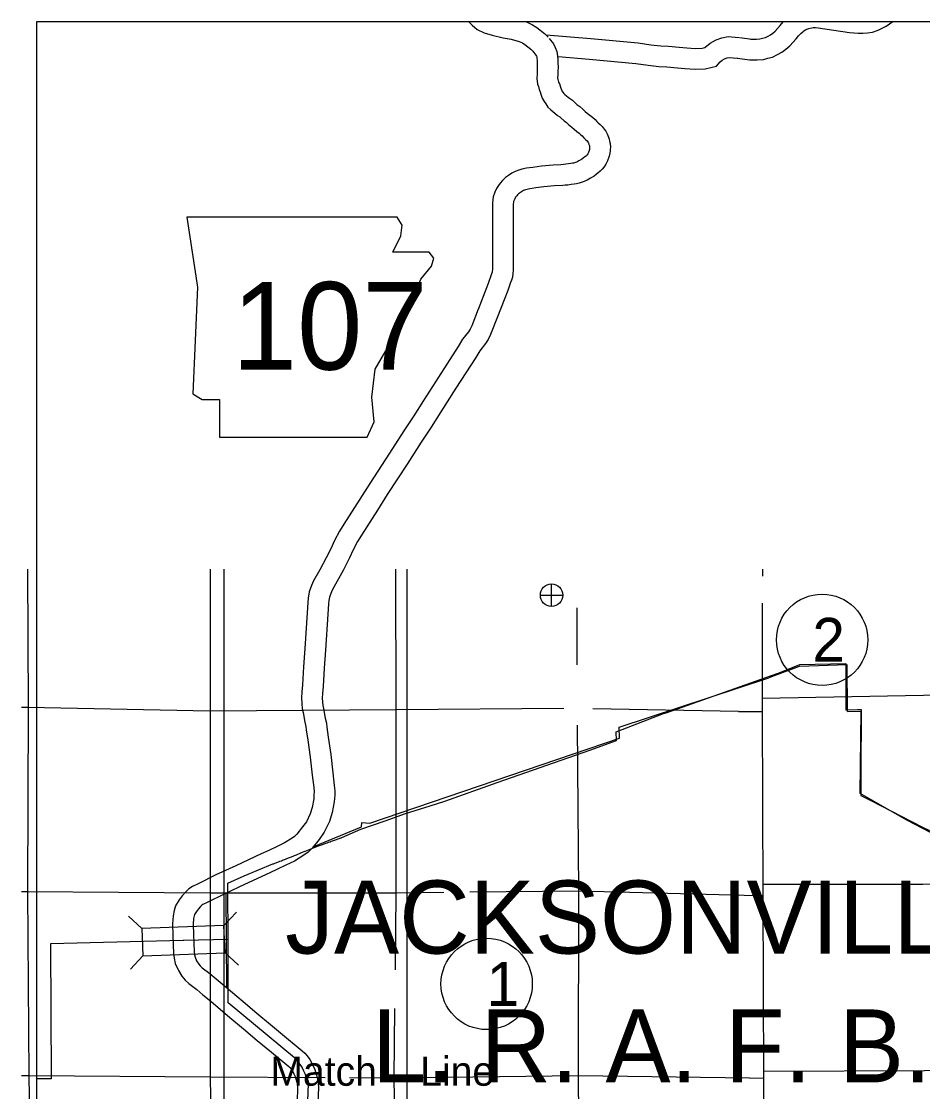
# Model space of a CAD drawing. Extents: x 1127717 to 1741049, y 2026793 to 2244711.
# Drawn here: x 1238326 to 1244840, y 2147909 to 2155644 of the extents above; entities that cross this region are included whole.
import ezdxf

# ---------------------------------------------------------------- set-up
doc = ezdxf.new("R2010")
doc.units = 0
for name, color, linetype in [('1', 7, 'Continuous'), ('10', 7, 'Continuous'), ('20', 7, 'Continuous'), ('21', 7, 'Continuous'), ('26', 7, 'Continuous'), ('27', 7, 'Continuous'), ('30', 7, 'Continuous'), ('4', 7, 'Continuous'), ('5', 7, 'Continuous'), ('58', 7, 'Continuous'), ('6', 7, 'Continuous'), ('7', 7, 'Continuous')]:
    doc.layers.add(name, color=color, linetype=linetype)

msp = doc.modelspace()

# ---------------------------------------------------------------- linework, layer by layer
at = {"layer": '1'}
msp.add_lwpolyline([(1238438.2, 2155644.2), (1269451.6, 2155644.2), (1269451.6, 2123596.1), (1238438.2, 2123596.1)], close=True, dxfattribs=at)
at = {"layer": '10'}
for points in [[(1241557.7, 2155644.2), (1241583.2, 2155615.8), (1241620.5, 2155586.1), (1241670.8, 2155562.5), (1241729.9, 2155544.7), (1241807.2, 2155526.2), (1241865.2, 2155515.5), (1241924.6, 2155499.4), (1241947.4, 2155488.5), (1241964.2, 2155478.1), (1242008.5, 2155443.1), (1242029, 2155422.7)], [(1241963.7, 2155644.2), (1241976.8, 2155640.6), (1242019.6, 2155620.3), (1242050.6, 2155601), (1242108.1, 2155555.6), (1242134.7, 2155529.2)], [(1243591, 2155366.7), (1243643.7, 2155366.1), (1243689.8, 2155369.7), (1243720.9, 2155378.4), (1243754.5, 2155386.5), (1243791.3, 2155403.9), (1243822.6, 2155421.2), (1243851.2, 2155442.7), (1243879.6, 2155466.7), (1243925.4, 2155518.7), (1243942.2, 2155539.5), (1243960.2, 2155557.1), (1243973.4, 2155569.6), (1243982.5, 2155577), (1243993.5, 2155583.8), (1244004.1, 2155589.2), (1244017.6, 2155592.2), (1244038.4, 2155598.5), (1244048.5, 2155600.6), (1244056.5, 2155601), (1244065.1, 2155601), (1244084.2, 2155597.4), (1244310.3, 2155565.2), (1244373.8, 2155558.4), (1244407.3, 2155558.5), (1244441.9, 2155562.2), (1244478.2, 2155567.3), (1244519.8, 2155579.8), (1244575.7, 2155610), (1244601.5, 2155626.9), (1244624, 2155644.2)], [(1243597, 2155516.6), (1243638.7, 2155516.1), (1243663.5, 2155518.1), (1243683.1, 2155523.6), (1243704.2, 2155528.7), (1243722.9, 2155537.5), (1243741, 2155547.5), (1243757.7, 2155560.1), (1243774.4, 2155574.2), (1243810.7, 2155615.4), (1243831, 2155640.6), (1243834.7, 2155644.2)], [(1242118.7, 2155548.1), (1242441.9, 2155520.2), (1242785.2, 2155489.3), (1242875.3, 2155475.6), (1242946.8, 2155468.4), (1243002.4, 2155464.5), (1243080.1, 2155458.6), (1243134.9, 2155453.5), (1243196.7, 2155448.3), (1243246.5, 2155451.3), (1243266.4, 2155456.1), (1243304.1, 2155486.5), (1243347.2, 2155512.1), (1243387.7, 2155524.8), (1243434.3, 2155536), (1243484.3, 2155529.5), (1243514.7, 2155527.5)], [(1242141.2, 2155521.8), (1242172.2, 2155481.6), (1242185.1, 2155456.7), (1242197.3, 2155427.8), (1242201.3, 2155392.9), (1242203.2, 2155365.6), (1242203.8, 2155341.8), (1242205, 2155315.5), (1242203.8, 2155281.4), (1242203.3, 2155258.8), (1242201.9, 2155236.4), (1242203.3, 2155224.5), (1242206.8, 2155214.5), (1242208.7, 2155206.2), (1242215.9, 2155193.1), (1242225.3, 2155162.2), (1242229.4, 2155148.7), (1242233, 2155142.5), (1242239.9, 2155131.7), (1242245.6, 2155123.8), (1242253, 2155116.7), (1242265.2, 2155106.5), (1242277.5, 2155095.7), (1242286.7, 2155088.4), (1242309.1, 2155075.3), (1242328.7, 2155055.9), (1242341.6, 2155044), (1242362.3, 2155029.9), (1242383.9, 2155008.8), (1242401.1, 2154993.3), (1242416.5, 2154980.9), (1242434.6, 2154965.5), (1242453.6, 2154951.6), (1242472.6, 2154934.1), (1242485, 2154921.3), (1242495.1, 2154911.3), (1242508.3, 2154898.7), (1242523.5, 2154883.6), (1242538.8, 2154866.2), (1242549.5, 2154850.1), (1242560.4, 2154830.5), (1242568.7, 2154808.6), (1242574.2, 2154794.1), (1242578, 2154778.1), (1242581.1, 2154761.7), (1242584.4, 2154735.3), (1242582.5, 2154719.7), (1242582.2, 2154708.2), (1242579.4, 2154690.7), (1242574.9, 2154669.4), (1242562.9, 2154636), (1242549.9, 2154611.9), (1242538.5, 2154594.2), (1242524.8, 2154576.2), (1242509.5, 2154561.7), (1242492.5, 2154547.4), (1242482.1, 2154539.4), (1242465, 2154524.6), (1242440, 2154510.3), (1242427.2, 2154504.9), (1242415.4, 2154497), (1242393.6, 2154486.7), (1242378.1, 2154481.7), (1242357.2, 2154474.3), (1242337.3, 2154471.2), (1242322.4, 2154467.9), (1242299.9, 2154465.6), (1242275.3, 2154461.6), (1242257.2, 2154461.1), (1242238.7, 2154458.1), (1242179.7, 2154456), (1242103, 2154448.1), (1242044.1, 2154440.8), (1242018.1, 2154436.4), (1242000.5, 2154434.6), (1241981.2, 2154430.4), (1241970, 2154427), (1241955.4, 2154421.6), (1241947.5, 2154417.7), (1241933.3, 2154407.9), (1241920, 2154398.1), (1241912, 2154391), (1241906.6, 2154384.2), (1241898.6, 2154373.4), (1241891.9, 2154362.6), (1241886.6, 2154352), (1241883.8, 2154343.3), (1241882.9, 2154336.9), (1241881.7, 2154323.3), (1241880.5, 2154300.4), (1241880.1, 2154280.2), (1241880, 2154245.5), (1241880.9, 2153986.5), (1241880, 2153847.4), (1241878.8, 2153823), (1241875.5, 2153796.8), (1241868.2, 2153773.5), (1241861.4, 2153757.7), (1241841.8, 2153698.9), (1241814.5, 2153631.7), (1241768.1, 2153509.6)], [(1243519.1, 2155527.1), (1243605.7, 2155516)], [(1242022.5, 2155430.2), (1242045.2, 2155400.7), (1242049.2, 2155393), (1242050.8, 2155389.2), (1242051.9, 2155379.2), (1242053.3, 2155358.6), (1242053.9, 2155336.3), (1242054.9, 2155314.7), (1242053.8, 2155285.6), (1242053.4, 2155265.1), (1242051.3, 2155232.3), (1242056.3, 2155190.4), (1242062.6, 2155172.6), (1242067.4, 2155152.1), (1242076.9, 2155134.6), (1242081.7, 2155118.8), (1242090.8, 2155088.6), (1242105, 2155064.3), (1242115.7, 2155047.5), (1242131.8, 2155025), (1242153, 2155004.8), (1242167.4, 2154992.7), (1242181.6, 2154980.2), (1242202, 2154964.2), (1242217, 2154955.4), (1242225.1, 2154947.4), (1242248, 2154926.3), (1242266.9, 2154913.4), (1242281.1, 2154899.5), (1242303.8, 2154879), (1242321, 2154865.3), (1242341.6, 2154847.7), (1242358.3, 2154835.5), (1242367.8, 2154826.7), (1242378.1, 2154816.1), (1242390.5, 2154803.8), (1242403.9, 2154791), (1242414.2, 2154780.8), (1242419.5, 2154774.8), (1242421.3, 2154772.1), (1242424, 2154767.1), (1242428.5, 2154755.3), (1242430.5, 2154750), (1242431.2, 2154747), (1242432.8, 2154738.6), (1242433.3, 2154735), (1242432.7, 2154730.6), (1242432.5, 2154722), (1242431.9, 2154718.4), (1242430.3, 2154710.5), (1242425.5, 2154697.3), (1242420.5, 2154688), (1242415.5, 2154680.2), (1242412.9, 2154676.8), (1242409.6, 2154673.7), (1242398.4, 2154664.2), (1242387.2, 2154655.6), (1242378, 2154647.6), (1242373.5, 2154645.1), (1242355.7, 2154637.6), (1242341.1, 2154627.8), (1242338.2, 2154626.4), (1242330, 2154623.8), (1242320.2, 2154620.3), (1242309.4, 2154618.6), (1242298.5, 2154616.2), (1242280.2, 2154614.4), (1242261.1, 2154611.2), (1242243.3, 2154610.7), (1242224.1, 2154607.7), (1242169.4, 2154605.7), (1242086, 2154597.2), (1242022.5, 2154589.2), (1241998, 2154585.2), (1241976.7, 2154582.9), (1241943.5, 2154575.7), (1241922, 2154569.2), (1241896.1, 2154559.5), (1241871.5, 2154547.5), (1241846.5, 2154530.2), (1241825.6, 2154515), (1241802.4, 2154494.2), (1241787.5, 2154475.4), (1241774.3, 2154457.6), (1241760.9, 2154435.9), (1241747.3, 2154408.9), (1241737.2, 2154377.1), (1241733.9, 2154354.4), (1241732, 2154333.9), (1241730.5, 2154305.7), (1241730.1, 2154281.8), (1241730, 2154245.4), (1241730.9, 2153986.8), (1241730, 2153851.5), (1241729.2, 2153835.9), (1241728.4, 2153828.9), (1241727.5, 2153826), (1241721.1, 2153811.3), (1241701, 2153750.9), (1241674.8, 2153686.5), (1241627.9, 2153562.8)], [(1242204.7, 2155390.1), (1242428.7, 2155370.8), (1242767.2, 2155340.3), (1242856.5, 2155326.8), (1242934, 2155319), (1242991.4, 2155314.9), (1243067.5, 2155309.1), (1243121.7, 2155304.1), (1243194.9, 2155297.9), (1243268.7, 2155302.3), (1243349.5, 2155321.8), (1243376.5, 2155352.2), (1243390, 2155363), (1243408.8, 2155374.2), (1243427.7, 2155380.1), (1243442.5, 2155383.7), (1243469.6, 2155380.2), (1243504.6, 2155377.8)], [(1243500.2, 2155378.3), (1243591, 2155366.7)], [(1241628.3, 2153563.7), (1241580.7, 2153443.2), (1241568.6, 2153420.6), (1241556.6, 2153401), (1241514.9, 2153347), (1241483.6, 2153294.9), (1241341, 2153073.7), (1241231.5, 2152903.1), (1241162.3, 2152793), (1241091.1, 2152684.8), (1240987.5, 2152524.7), (1240844.4, 2152305.2), (1240772.5, 2152191.4), (1240656, 2152010.7), (1240625.8, 2151959.8), (1240589.3, 2151892), (1240561.8, 2151832.9), (1240529.7, 2151767.5), (1240482.2, 2151680.4)], [(1241767.8, 2153508.7), (1241717.1, 2153380.2), (1241698.8, 2153345.9), (1241680.2, 2153315.6), (1241639, 2153262.2), (1241611, 2153215.6), (1241467.1, 2152992.5), (1241358.1, 2152822.7), (1241288.5, 2152711.8), (1241216.7, 2152602.8), (1241113.3, 2152443), (1240970.7, 2152224.1), (1240898.9, 2152110.7), (1240783.6, 2151931.7), (1240756.4, 2151886), (1240723.5, 2151824.7), (1240697.2, 2151768.2), (1240663, 2151698.6), (1240653.2, 2151680.6)], [(1240482.2, 2151680.4), (1240438.5, 2151600.2), (1240422.9, 2151566.7), (1240406.5, 2151521.5), (1240398.5, 2151475.5), (1240397.1, 2151443), (1240392.1, 2151370), (1240375.5, 2151110.6), (1240365.5, 2150979.7), (1240356.9, 2150848.1), (1240353.3, 2150797.5), (1240350.5, 2150754.6), (1240352.7, 2150714.9), (1240356.1, 2150676.6), (1240362, 2150648.8), (1240375.8, 2150578.4), (1240382.1, 2150547.7), (1240385, 2150523.3), (1240396.1, 2150449.8), (1240413.7, 2150325.3), (1240428.9, 2150196.2), (1240438.7, 2150106.1), (1240441.2, 2150076.7), (1240440.9, 2150056.4), (1240440.1, 2150037.4), (1240439, 2150024.5), (1240426.9, 2149962.9), (1240412.7, 2149916), (1240385.8, 2149859.9), (1240359, 2149822), (1240316.6, 2149769.1), (1240300.5, 2149753.6), (1240284, 2149741.2), (1240227.7, 2149706.3), (1240173.7, 2149680.1), (1240114.7, 2149652.8), (1240059.4, 2149627.2), (1239875.6, 2149541.6), (1239731.9, 2149474.7), (1239603, 2149411), (1239562.2, 2149391.4), (1239537.3, 2149373.8), (1239515.4, 2149354.1), (1239488.7, 2149325.2), (1239467.1, 2149294.2), (1239440.7, 2149252.8), (1239429.6, 2149217), (1239422.3, 2149178.6), (1239418.5, 2149121.4), (1239420.7, 2149040), (1239425.7, 2148906.9), (1239429.6, 2148874.6), (1239437.6, 2148834.3), (1239460.9, 2148783.6), (1239486.2, 2148743.7), (1239509, 2148715.4), (1239536.2, 2148689.6), (1239593.7, 2148646.4), (1239638.3, 2148608.2), (1239694.4, 2148561.7), (1239832.3, 2148444.2), (1239932.4, 2148361.6), (1240031.3, 2148278.8), (1240132.9, 2148194.4), (1240230.2, 2148113.5), (1240259, 2148089.4), (1240267.1, 2148082.3), (1240273.2, 2148074.8), (1240284.6, 2148059.4), (1240296.1, 2148038.4), (1240305.1, 2148017.3), (1240317, 2147976.7), (1240321.4, 2147952.4), (1240322.5, 2147934.2), (1240318.8, 2147842.1)], [(1240653.2, 2151680.6), (1240572.5, 2151532.6), (1240561.7, 2151509.3), (1240552, 2151482.7), (1240547.9, 2151459.3), (1240546.8, 2151434.6), (1240541.7, 2151360.1), (1240525.1, 2151100.1), (1240515.1, 2150969.1), (1240506.6, 2150837.9), (1240502.9, 2150787.2), (1240500.8, 2150753.9), (1240502.3, 2150725.6), (1240504.7, 2150699), (1240509, 2150678.9), (1240522.9, 2150607.9), (1240530.3, 2150571.9), (1240533.7, 2150543.4), (1240544.5, 2150471.4), (1240562.4, 2150344.6), (1240578, 2150213.1), (1240588, 2150120.5), (1240591.3, 2150082), (1240590.9, 2150052.2), (1240589.8, 2150028.1), (1240587.9, 2150003.9), (1240572.7, 2149926.6), (1240552.9, 2149861.5), (1240515.6, 2149783.6), (1240478.9, 2149731.7), (1240427.7, 2149667.9), (1240398, 2149639.1), (1240368.6, 2149617.2), (1240300.2, 2149574.7), (1240237.9, 2149544.6), (1240177.7, 2149516.7), (1240122.6, 2149491.2), (1239938.9, 2149405.6), (1239796.8, 2149339.5), (1239668.7, 2149276.1), (1239638.5, 2149261.7), (1239631.1, 2149256.4), (1239620.9, 2149247.2), (1239605.9, 2149231), (1239591.9, 2149210.9), (1239578, 2149189.1), (1239575.4, 2149180.5), (1239571.3, 2149159.5), (1239568.7, 2149118.5), (1239570.6, 2149044.8), (1239575.4, 2148918.8), (1239577.9, 2148898.2), (1239581.3, 2148880.8), (1239593, 2148855.3), (1239608.3, 2148831.3), (1239619.5, 2148817.4), (1239633.2, 2148804.3), (1239687.6, 2148763.4), (1239734.9, 2148723), (1239791, 2148676.5), (1239928.6, 2148559.2), (1240028.3, 2148477), (1240127.4, 2148394), (1240228.7, 2148309.7), (1240326.2, 2148228.7), (1240356.6, 2148203.3), (1240375, 2148187.1), (1240391.5, 2148167.1), (1240411.3, 2148140.3), (1240431.2, 2148104.1), (1240446.6, 2148067.9), (1240463.2, 2148011.1), (1240470.5, 2147970.6), (1240472.7, 2147935.9), (1240468.6, 2147833.5)]]:
    msp.add_lwpolyline(points, dxfattribs=at)
at = {"layer": '20'}
for p, q in [((1239790.3, 2149110), (1239880, 2149206.8)), ((1239196.7, 2149087.5), (1239099.9, 2149177.3)), ((1239204.2, 2148889.7), (1239114.5, 2148792.9)), ((1239797.8, 2148912.2), (1239894.6, 2148822.4))]:
    msp.add_line(p, q, dxfattribs=at)
msp.add_lwpolyline([(1239204.2, 2148889.7), (1239797.8, 2148912.2), (1239790.3, 2149110), (1239196.7, 2149087.5)], close=True, dxfattribs=at)
at = {"layer": '21'}
msp.add_lwpolyline([(1239521.8, 2154230.1), (1239597.9, 2153722.6), (1239564.1, 2152952.8), (1239631.8, 2152910.5), (1239758.6, 2152910.5), (1239758.6, 2152639.8), (1240824.5, 2152639.8), (1240875.2, 2152749.8), (1240858.3, 2152927.4), (1240883.7, 2153130.4), (1240976.7, 2153291.2), (1241035.9, 2153409.6), (1241120.5, 2153536.5), (1241171.3, 2153671.8), (1241213.6, 2153781.8), (1241289.7, 2153874.8), (1241306.6, 2153934), (1241272.8, 2153976.3), (1241010.6, 2153976.3), (1241069.8, 2154094.8), (1241078.2, 2154170.9), (1241043.2, 2154229.3)], close=True, dxfattribs=at)
at = {"layer": '26'}
for p, q in [((1242158.2, 2151415.8), (1242158.2, 2151578.3)), ((1242076.9, 2151497), (1242239.4, 2151497))]:
    msp.add_line(p, q, dxfattribs=at)
msp.add_circle((1242158.2, 2151497), 81.2, dxfattribs=at)
at = {"layer": '27'}
for centre in [(1244113.6, 2151174.5), (1241688.8, 2148687.3)]:
    msp.add_circle(centre, 330, dxfattribs=at)
at = {"layer": '30'}
for p, q in [((1239791.2, 2119636.1), (1239791.2, 2151684.2)), ((1241111.2, 2151684.2), (1241111.2, 2119636.1))]:
    msp.add_line(p, q, dxfattribs=at)
at = {"layer": '4'}
for points in [[(1243681.7, 2151684.2), (1243681.6, 2151635.4)], [(1243681.3, 2151440.5), (1243680.1, 2150655.8), (1243685.7, 2149325.8), (1243689, 2148006.4), (1243690.2, 2147724.8)]]:
    msp.add_lwpolyline(points, dxfattribs=at)
at = {"layer": '5'}
for points in [[(1238369.7, 2151684.2), (1238374.3, 2150685.2), (1238369.4, 2149354), (1238381, 2148022.7), (1238384.5, 2147717.8)], [(1239697.3, 2147719.5), (1239692.1, 2148012.3), (1239693.3, 2149347.5), (1239692.7, 2150658), (1239691.9, 2151684.2)], [(1241030.9, 2151684.2), (1241032.7, 2150666.5), (1241033.5, 2149344.9), (1241026.7, 2148789.5)], [(1242343.8, 2150993.4), (1242342.2, 2151406.1)], [(1243680.3, 2150753.3), (1244846.8, 2150773.7), (1246169.6, 2150785.1), (1246712.4, 2150788.2)], [(1242247.7, 2150677.9), (1241034.6, 2150668), (1239688.7, 2150659.4), (1238372.2, 2150686.2), (1238326.3, 2150686.1)], [(1243509.1, 2150655.5), (1242456.8, 2150676.5)], [(1243509.1, 2150655.5), (1243679.6, 2150655.7)], [(1242354.3, 2147723.1), (1242352.2, 2148022.1), (1242354.5, 2149355.8), (1242345.9, 2150557.8)], [(1243688.9, 2149407.7), (1244842, 2149407.9), (1246168.1, 2149410.8), (1247390.4, 2149448)], [(1238326.3, 2149355.2), (1238366.4, 2149355.4), (1239691.3, 2149346.9), (1241035, 2149346.9), (1241379.2, 2149350.2)], [(1241568.4, 2149351.9), (1242354.9, 2149359.3), (1243550.1, 2149329.9)], [(1243550.1, 2149329.9), (1243685.2, 2149326.8)], [(1241023.2, 2148508.6), (1241016.9, 2148005.8), (1241022.4, 2147721.3)], [(1243688.9, 2148057.5), (1244852.4, 2148062), (1246161.1, 2148081.6), (1247175.4, 2148099.6)], [(1240520.8, 2148009.1), (1239690, 2148013.8), (1238382.5, 2148023.7), (1238326.3, 2148023.6)], [(1243587.5, 2148006.6), (1242352.2, 2148022.1), (1241017.9, 2148006.3), (1240698.6, 2148008.1)], [(1243587.5, 2148006.6), (1243688.9, 2148008.9)]]:
    msp.add_lwpolyline(points, dxfattribs=at)
at = {"layer": '6'}
for points in [[(1240396.3, 2147839.5), (1240400.2, 2147967.7), (1240400.8, 2147985.9), (1240393.8, 2147985.8), (1240390.7, 2147985.7), (1240389.4, 2147990.9), (1240378.7, 2148032.3), (1240370.5, 2148051.6), (1240368, 2148057.1), (1240367.5, 2148058.3), (1240366.4, 2148060.7), (1240365.7, 2148062.2), (1240364.7, 2148064.5), (1240364, 2148066), (1240361.2, 2148072.1), (1240360.6, 2148073.5), (1240359.9, 2148074.9), (1240359.1, 2148076.8), (1240358.2, 2148078.7), (1240357, 2148081.3), (1240356.2, 2148083.1), (1240355.2, 2148085.2), (1240324.9, 2148126.8), (1240299, 2148153.4), (1239821.8, 2148551.5), (1239820.1, 2149007.7), (1239818.7, 2149378.6), (1239818.6, 2149414.6), (1239935.9, 2149468), (1240144, 2149555.2), (1240145.8, 2149555.9), (1240147.5, 2149556.5), (1240171, 2149565.4), (1240172.1, 2149565.8), (1240184.4, 2149570.2), (1240184.6, 2149570.3), (1240193.4, 2149573.5), (1240205.6, 2149577.9), (1240213.1, 2149581), (1240221.7, 2149584.3), (1240234, 2149589.1), (1240245.3, 2149593.4), (1240289.5, 2149610.8), (1240299.9, 2149614.9), (1240314.3, 2149620), (1240325.3, 2149625.3), (1240336.6, 2149630.8), (1240349.7, 2149637.4), (1240377.4, 2149647.5), (1240460.6, 2149679.8), (1240474.4, 2149684.3), (1240481, 2149686.9), (1240495.3, 2149692.2), (1240502.7, 2149694.8), (1240522.2, 2149702.2), (1240535.2, 2149706.4), (1240546.4, 2149711), (1240559, 2149715.5), (1240566.3, 2149718.1), (1240574.4, 2149721.2), (1240583, 2149724.4), (1240596, 2149729.8), (1240634.8, 2149743), (1240637.8, 2149743.5), (1240639.3, 2149743.7), (1240639.3, 2149743.7), (1240640.6, 2149744.7), (1240641.7, 2149745.5), (1240779.6, 2149805.6), (1240954.6, 2149867), (1241103.5, 2149919.2), (1241280.1, 2149974.4), (1241386.2, 2150007.5), (1241763.9, 2150142.4), (1242434.4, 2150377.3), (1242626.5, 2150447.2), (1242624, 2150510.5), (1242967.7, 2150641.2), (1242985.2, 2150647.8), (1243789.1, 2150930.4), (1243798.8, 2150934.3), (1243802.4, 2150935.8), (1243952.9, 2150996.3)], [(1243952.9, 2150996.3), (1244284.9, 2151002.9), (1244285.2, 2150879.2), (1244285.6, 2150669), (1244288.7, 2150669), (1244368.3, 2150670.5), (1244395.2, 2150670.9), (1244394.8, 2150559.1), (1244394.7, 2150555), (1244394.7, 2150546.8), (1244393.9, 2150325.3), (1244394.3, 2150048.6), (1244408.7, 2150041.3), (1244465.6, 2150012.2), (1244839.7, 2149821.3), (1244890.7, 2149795.3)], [(1239820.1, 2149007.7), (1239501.4, 2149000.4), (1239498.4, 2149000.3), (1239495.5, 2149000.3), (1238536.8, 2148978.3), (1238540.6, 2148002.1), (1238438.2, 2148002)], [(1240396.3, 2147839.5), (1240400.2, 2147967.7), (1240400.8, 2147985.9), (1240393.8, 2147985.8), (1240390.7, 2147985.7), (1240389.4, 2147990.9), (1240378.7, 2148032.3), (1240370.5, 2148051.6), (1240368, 2148057.1), (1240367.5, 2148058.3), (1240366.4, 2148060.7), (1240365.7, 2148062.2), (1240364.7, 2148064.5), (1240364, 2148066), (1240361.2, 2148072.1), (1240360.6, 2148073.5), (1240359.9, 2148074.9), (1240359.1, 2148076.8), (1240358.2, 2148078.7), (1240357, 2148081.3), (1240356.2, 2148083.1), (1240355.2, 2148085.2), (1240324.9, 2148126.8), (1240299, 2148153.4), (1239821.8, 2148551.5), (1239820.1, 2149007.7)]]:
    msp.add_lwpolyline(points, dxfattribs=at)
at = {"layer": '7'}
for points in [[(1244296.5, 2150656.2), (1244295, 2150993.9), (1243948.2, 2150981.8), (1243728.9, 2150900.2)], [(1240438.7, 2149680.7), (1240785.3, 2149823.9), (1240786.5, 2149852.9), (1240843.5, 2149849), (1242648.8, 2150463.8), (1242647.2, 2150542.8), (1243728.9, 2150900.2)], [(1244296.5, 2150656.2), (1244396.8, 2150659)], [(1245530.3, 2149468.5), (1245068.9, 2149693.4), (1244726.2, 2149872.1), (1244388.6, 2150062.9), (1244396.8, 2150659)], [(1239804.9, 2149340.4), (1239807.6, 2148661.1)]]:
    msp.add_lwpolyline(points, dxfattribs=at)

# ---------------------------------------------------------------- texts
at = {"layer": '21'}
msp.add_text('107', height=633.6, dxfattribs=at).set_placement((1239848.2, 2153127))
at = {"layer": '27'}
for s, height, p in [('2', 316.8, (1244042.8, 2151016.1)), ('1', 316.8, (1241688.8, 2148528.9)), ('Match    Line', 211.2, (1240126.3, 2147951.3))]:
    msp.add_text(s, height=height, dxfattribs=at).set_placement(p)
at = {"layer": '58'}
msp.add_text('Match    Line', height=211.2, dxfattribs=at).set_placement((1240126.3, 2147951.3))
at = {"layer": '6'}
msp.add_text('JACKSONVILLE', height=527.999, dxfattribs=at).set_placement((1240232.5, 2148906.7))
at = {"layer": '7'}
msp.add_text('L. R. A. F. B.', height=527.999, dxfattribs=at).set_placement((1240860.2, 2147975.6))

doc.saveas('drawing.dxf')
